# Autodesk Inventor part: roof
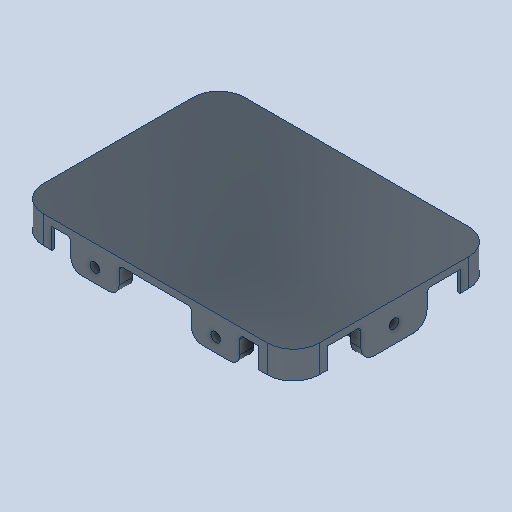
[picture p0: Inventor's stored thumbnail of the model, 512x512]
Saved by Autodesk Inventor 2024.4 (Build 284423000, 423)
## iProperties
Created: 2025-07
Part Number: roof
Material: Generic
Document SubType Name: Modeling
Designer: AdminForWorker
Density: 1 g/cm^3
Appearance: Default
Title: roof v2
Author: AdminForWorker
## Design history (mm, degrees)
feature "Body1"
body "Solid1"
